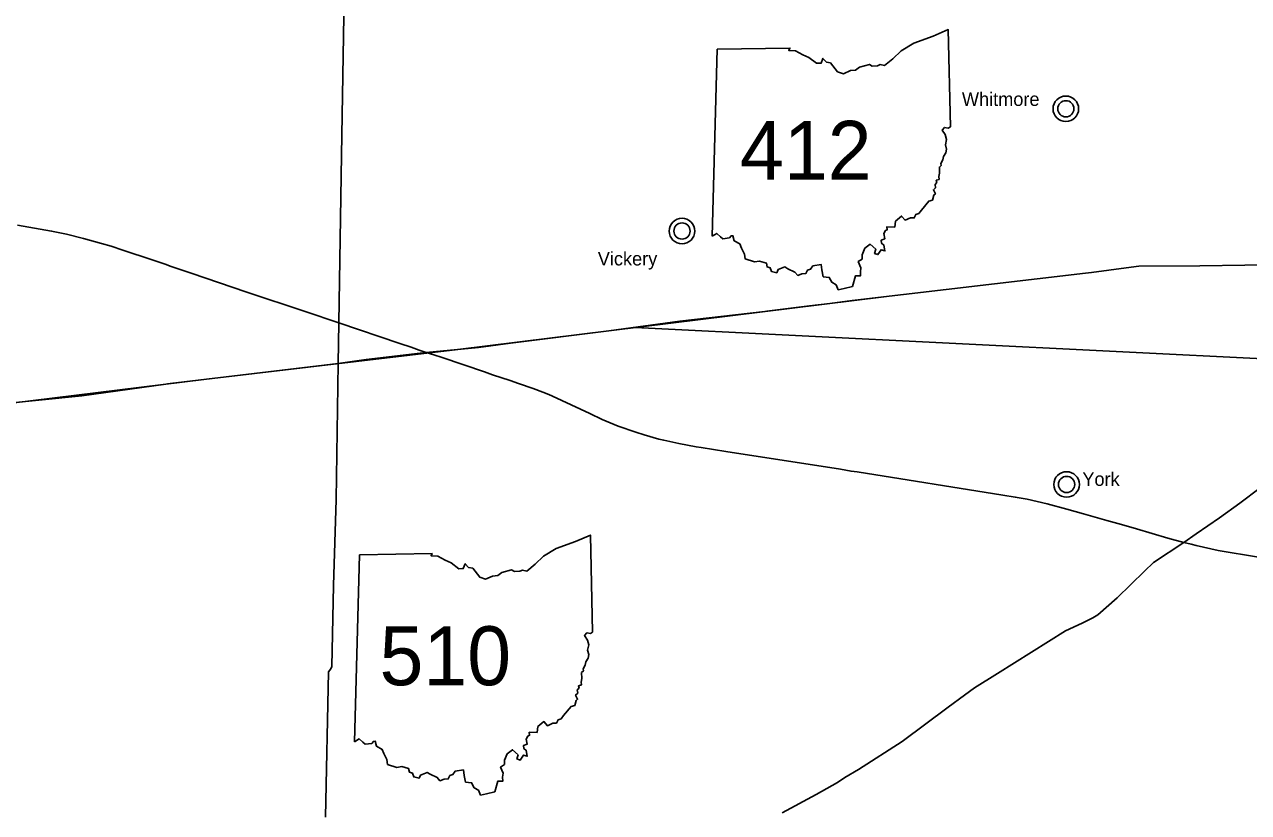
# Model space of a CAD drawing. Extents: x 0 to 798, y 0 to 440.
# Drawn here: x 446.4 to 540.4, y 195.7 to 256.2 of the extents above; entities that cross this region are included whole.
import ezdxf

# ---------------------------------------------------------------- set-up
doc = ezdxf.new("R2010")
doc.units = 0
for name, color, linetype in [('DV_X_Corp_Line', 7, 'Continuous'), ('GM_X_Interstate_Route', 7, 'Continuous'), ('GM_X_State_Route', 7, 'Continuous'), ('PV_P_Text', 7, 'Continuous'), ('SH_Data', 7, 'Continuous'), ('SH_Text', 7, 'Continuous')]:
    doc.layers.add(name, color=color, linetype=linetype)

msp = doc.modelspace()

# ---------------------------------------------------------------- linework, layer by layer
at = {"layer": 'DV_X_Corp_Line'}
for centre, radius in [((526.341, 249.752), 0.982), ((526.341, 249.752), 0.623), ((496.864, 240.36), 0.982), ((496.864, 240.36), 0.623), ((526.399, 220.893), 0.982), ((526.399, 220.893), 0.623)]:
    msp.add_circle(centre, radius, dxfattribs=at)
at = {"layer": 'GM_X_Interstate_Route'}
for points in [[(445.845, 240.82), (448.444, 240.358), (449.603, 240.115), (450.914, 239.792), (452.29, 239.407), (453.016, 239.192), (453.921, 238.897), (456.175, 238.137), (457.176, 237.804), (457.368, 237.73), (457.553, 237.674), (459.177, 237.127), (463.457, 235.671), (467.932, 234.185), (470.519, 233.299)], [(470.519, 233.299), (475.186, 231.729), (476.063, 231.433), (476.687, 231.22), (477.227, 231.041)], [(477.227, 231.041), (477.811, 230.84), (478.442, 230.637), (481.691, 229.535), (482.314, 229.323), (483.661, 228.872), (484.316, 228.656), (485.44, 228.259), (486.173, 227.973), (486.627, 227.791), (486.906, 227.668), (487.633, 227.346), (489.777, 226.332), (490.736, 225.881), (491.962, 225.383), (493.327, 224.902), (493.95, 224.699), (495.096, 224.383), (495.462, 224.29), (496.625, 224.031), (497.942, 223.795), (498.334, 223.739), (500.24, 223.434), (509.044, 222.058), (509.85, 221.913), (510.328, 221.85), (521.502, 220.07), (522.453, 219.927), (523.359, 219.75), (524.902, 219.406), (526.429, 219.001), (527.708, 218.647), (529.484, 218.129), (530.623, 217.805), (531.768, 217.472), (534.176, 216.778), (535.411, 216.436)], [(535.411, 216.436), (535.959, 216.296), (536.343, 216.195), (538.049, 215.818), (541.14, 215.309), (543.103, 215.027), (545.19, 214.727), (546.631, 214.512), (549.5, 214.099), (552.898, 213.603), (555.121, 213.284), (557.773, 212.9), (566.971, 211.135)]]:
    msp.add_lwpolyline(points, dxfattribs=at)
at = {"layer": 'GM_X_State_Route'}
msp.add_line((510.15, 235.049), (527.849, 237.123), dxfattribs=at)
for points in [[(469.488, 195.343), (469.722, 206.488), (469.906, 206.741), (469.984, 206.905), (470.105, 213.119), (470.31, 219.731), (470.468, 230.182), (470.519, 233.299), (470.702, 246.178), (471.047, 266.057)], [(527.849, 237.123), (528.301, 237.175), (530.968, 237.527), (531.941, 237.654), (536.639, 237.679), (540.086, 237.731), (543.32, 237.756), (545.306, 237.722), (545.783, 237.707), (546.098, 237.766), (546.711, 238.041), (547.144, 237.988), (548.24, 237.714), (552.16, 234.851), (553.376, 233.926), (554.473, 233.191), (556.089, 231.972), (556.243, 231.87), (556.425, 231.423)], [(476.972, 231.01), (477.227, 231.041), (481.223, 231.411), (483.689, 231.738), (491.253, 232.695), (496.687, 233.426), (503.225, 234.19), (503.37, 234.207), (506.663, 234.612), (508.227, 234.805), (509.934, 235.022)], [(509.934, 235.022), (509.954, 235.024), (510.15, 235.049)], [(535.411, 216.436), (536.355, 217.089), (538.148, 218.33), (539.714, 219.452), (541.254, 220.634), (544.23, 222.901), (546.831, 224.934), (548.888, 226.573), (551.092, 228.229), (552.014, 228.932), (552.448, 229.223), (553.861, 229.967), (556.425, 231.423)], [(470.468, 230.182), (472.603, 230.483), (476.972, 231.01)], [(457.362, 228.622), (457.567, 228.651), (470.468, 230.182)], [(443.735, 226.99), (444.137, 227.042), (450.764, 227.697), (457.232, 228.604), (457.362, 228.622)], [(504.554, 195.674), (507.169, 197.074), (508.795, 198.003), (509.377, 198.383), (510.427, 198.988), (513.768, 201.157), (517.301, 203.79), (518.57, 204.714), (519.33, 205.267), (521.083, 206.364), (526.312, 209.637), (527.594, 210.239), (528.422, 210.656), (528.796, 210.877), (530.281, 212.185), (532.387, 214.243), (533.076, 214.888), (535.411, 216.436)]]:
    msp.add_lwpolyline(points, dxfattribs=at)
at = {"layer": 'PV_P_Text'}
for p, q in [((499.171, 239.957), (499.573, 254.32)), ((499.171, 239.957), (499.573, 254.32)), ((471.701, 201.13), (472.103, 215.493)), ((471.701, 201.13), (472.103, 215.493))]:
    msp.add_line(p, q, dxfattribs=at)
for points in [[(499.573, 254.32), (505.145, 254.414), (505.058, 254.24), (505.584, 254.203), (506.143, 253.897), (506.615, 253.703), (507.193, 253.246), (507.539, 253.251), (507.685, 253.626), (507.95, 253.337), (508.264, 253.285), (508.807, 252.598), (509.256, 252.449), (509.793, 252.684), (510.194, 252.723), (510.488, 252.956), (511.252, 253.155), (511.466, 253.036), (511.87, 253.06), (512.074, 253.148), (512.427, 253.069), (513.049, 253.591), (513.689, 254.207), (514.673, 254.788), (516.143, 255.339), (517.305, 255.831), (517.473, 248.378)], [(499.573, 254.32), (505.145, 254.414), (505.058, 254.24), (505.584, 254.203), (506.143, 253.897), (506.615, 253.703), (507.193, 253.246), (507.539, 253.251), (507.685, 253.626), (507.95, 253.337), (508.264, 253.285), (508.807, 252.598), (509.256, 252.449), (509.793, 252.684), (510.194, 252.723), (510.488, 252.956), (511.252, 253.155), (511.466, 253.036), (511.87, 253.06), (512.074, 253.148), (512.427, 253.069), (513.049, 253.591), (513.689, 254.207), (514.673, 254.788), (516.143, 255.339), (517.305, 255.831), (517.473, 248.378)], [(517.473, 248.378), (517.302, 248.273), (517.035, 248.322), (516.855, 248.113), (517.077, 247.764), (517.182, 247.396), (517.089, 246.99), (517.181, 246.655), (517.119, 246.374), (516.951, 246.095), (516.893, 245.829), (516.75, 245.549), (516.762, 245.392), (516.626, 245.268), (516.651, 244.802), (516.582, 244.543), (516.605, 244.321), (516.385, 244.262), (516.435, 244.078), (516.295, 243.936), (516.325, 243.691), (516.166, 243.535), (516.32, 243.222), (516.196, 243.123), (516.093, 242.743), (515.81, 242.666), (515.244, 241.97), (515.044, 241.707), (514.819, 241.642), (514.695, 241.372), (514.419, 241.371), (514, 241.184), (513.729, 241.506), (513.255, 241.118), (513.201, 240.67), (512.601, 240.684), (512.625, 240.458), (512.491, 240.392), (512.369, 240.165), (512.44, 239.762), (512.159, 239.659), (512.193, 239.425), (512.373, 239.282), (512.453, 238.835), (512.154, 238.926), (511.91, 238.549), (511.659, 238.637), (511.741, 238.956), (511.317, 239.34), (510.915, 239.033), (510.705, 238.541), (510.703, 238.211), (510.404, 238.011), (510.596, 237.544), (510.561, 237.222), (510.566, 236.917), (510.192, 236.927), (509.966, 236.103)], [(517.473, 248.378), (517.302, 248.273), (517.035, 248.322), (516.855, 248.113), (517.077, 247.764), (517.182, 247.396), (517.089, 246.99), (517.181, 246.655), (517.119, 246.374), (516.951, 246.095), (516.893, 245.829), (516.75, 245.549), (516.762, 245.392), (516.626, 245.268), (516.651, 244.802), (516.582, 244.543), (516.605, 244.321), (516.385, 244.262), (516.435, 244.078), (516.295, 243.936), (516.325, 243.691), (516.166, 243.535), (516.32, 243.222), (516.196, 243.123), (516.093, 242.743), (515.81, 242.666), (515.244, 241.97), (515.044, 241.707), (514.819, 241.642), (514.695, 241.372), (514.419, 241.371), (514, 241.184), (513.729, 241.506), (513.255, 241.118), (513.201, 240.67), (512.601, 240.684), (512.625, 240.458), (512.491, 240.392), (512.369, 240.165), (512.44, 239.762), (512.159, 239.659), (512.193, 239.425), (512.373, 239.282), (512.453, 238.835), (512.154, 238.926), (511.91, 238.549), (511.659, 238.637), (511.741, 238.956), (511.317, 239.34), (510.915, 239.033), (510.705, 238.541), (510.703, 238.211), (510.404, 238.011), (510.596, 237.544), (510.561, 237.222), (510.566, 236.917), (510.192, 236.927), (509.966, 236.103)], [(509.966, 236.103), (509.315, 235.945), (508.864, 235.851), (508.705, 236.225), (508.382, 236.423), (508.172, 236.8), (507.708, 236.851), (507.598, 237.369), (507.547, 237.79), (506.913, 237.686), (506.739, 237.429), (506.514, 237.36), (506.384, 237.101), (506.077, 237.079), (505.748, 236.957), (505.533, 237.211), (504.994, 237.466), (504.752, 237.598), (504.246, 237.393), (504.138, 237.151), (503.735, 237.258), (503.64, 237.528), (503.396, 237.609), (503.342, 237.895), (502.821, 238.047), (502.422, 237.987), (501.719, 238.217), (501.676, 238.593), (501.436, 239.052), (501.311, 239.37), (500.866, 239.613), (500.776, 239.992), (500.634, 239.981), (500.504, 239.827), (500.01, 239.757), (499.813, 239.911), (499.536, 240.176), (499.171, 239.957)], [(509.966, 236.103), (509.315, 235.945), (508.864, 235.851), (508.705, 236.225), (508.382, 236.423), (508.172, 236.8), (507.708, 236.851), (507.598, 237.369), (507.547, 237.79), (506.913, 237.686), (506.739, 237.429), (506.514, 237.36), (506.384, 237.101), (506.077, 237.079), (505.748, 236.957), (505.533, 237.211), (504.994, 237.466), (504.752, 237.598), (504.246, 237.393), (504.138, 237.151), (503.735, 237.258), (503.64, 237.528), (503.396, 237.609), (503.342, 237.895), (502.821, 238.047), (502.422, 237.987), (501.719, 238.217), (501.676, 238.593), (501.436, 239.052), (501.311, 239.37), (500.866, 239.613), (500.776, 239.992), (500.634, 239.981), (500.504, 239.827), (500.01, 239.757), (499.813, 239.911), (499.536, 240.176), (499.171, 239.957)], [(472.103, 215.493), (477.675, 215.587), (477.588, 215.413), (478.114, 215.376), (478.673, 215.07), (479.145, 214.876), (479.723, 214.419), (480.069, 214.424), (480.215, 214.799), (480.48, 214.51), (480.794, 214.458), (481.337, 213.771), (481.786, 213.622), (482.323, 213.857), (482.724, 213.896), (483.017, 214.129), (483.782, 214.328), (483.996, 214.209), (484.4, 214.233), (484.604, 214.321), (484.957, 214.242), (485.579, 214.765), (486.219, 215.38), (487.203, 215.961), (488.673, 216.512), (489.835, 217.004), (490.003, 209.551)], [(472.103, 215.493), (477.675, 215.587), (477.588, 215.413), (478.114, 215.376), (478.673, 215.07), (479.145, 214.876), (479.723, 214.419), (480.069, 214.424), (480.215, 214.799), (480.48, 214.51), (480.794, 214.458), (481.337, 213.771), (481.786, 213.622), (482.323, 213.857), (482.724, 213.896), (483.017, 214.129), (483.782, 214.328), (483.996, 214.209), (484.4, 214.233), (484.604, 214.321), (484.957, 214.242), (485.579, 214.765), (486.219, 215.38), (487.203, 215.961), (488.673, 216.512), (489.835, 217.004), (490.003, 209.551)], [(490.003, 209.551), (489.832, 209.446), (489.565, 209.495), (489.385, 209.286), (489.607, 208.937), (489.712, 208.569), (489.619, 208.163), (489.711, 207.828), (489.649, 207.547), (489.481, 207.268), (489.423, 207.002), (489.28, 206.722), (489.292, 206.565), (489.156, 206.441), (489.181, 205.975), (489.112, 205.716), (489.135, 205.494), (488.915, 205.435), (488.965, 205.251), (488.825, 205.109), (488.855, 204.864), (488.696, 204.708), (488.85, 204.396), (488.726, 204.296), (488.623, 203.916), (488.34, 203.839), (487.774, 203.143), (487.574, 202.88), (487.349, 202.815), (487.225, 202.545), (486.949, 202.544), (486.53, 202.357), (486.259, 202.679), (485.785, 202.291), (485.731, 201.843), (485.131, 201.857), (485.155, 201.631), (485.021, 201.565), (484.899, 201.338), (484.97, 200.935), (484.689, 200.833), (484.723, 200.598), (484.903, 200.455), (484.983, 200.008), (484.684, 200.099), (484.44, 199.722), (484.189, 199.81), (484.271, 200.13), (483.847, 200.513), (483.445, 200.206), (483.235, 199.715), (483.233, 199.384), (482.934, 199.184), (483.126, 198.717), (483.091, 198.395), (483.096, 198.09), (482.722, 198.101), (482.496, 197.276)], [(490.003, 209.551), (489.832, 209.446), (489.565, 209.495), (489.385, 209.286), (489.607, 208.937), (489.712, 208.569), (489.619, 208.163), (489.711, 207.828), (489.649, 207.547), (489.481, 207.268), (489.423, 207.002), (489.28, 206.722), (489.292, 206.565), (489.156, 206.441), (489.181, 205.975), (489.112, 205.716), (489.135, 205.494), (488.915, 205.435), (488.965, 205.251), (488.825, 205.109), (488.855, 204.864), (488.696, 204.708), (488.85, 204.396), (488.726, 204.296), (488.623, 203.916), (488.34, 203.839), (487.774, 203.143), (487.574, 202.88), (487.349, 202.815), (487.225, 202.545), (486.949, 202.544), (486.53, 202.357), (486.259, 202.679), (485.785, 202.291), (485.731, 201.843), (485.131, 201.857), (485.155, 201.631), (485.021, 201.565), (484.899, 201.338), (484.97, 200.935), (484.689, 200.833), (484.723, 200.598), (484.903, 200.455), (484.983, 200.008), (484.684, 200.099), (484.44, 199.722), (484.189, 199.81), (484.271, 200.13), (483.847, 200.513), (483.445, 200.206), (483.235, 199.715), (483.233, 199.384), (482.934, 199.184), (483.126, 198.717), (483.091, 198.395), (483.096, 198.09), (482.722, 198.101), (482.496, 197.276)], [(482.496, 197.276), (481.845, 197.118), (481.394, 197.024), (481.235, 197.399), (480.912, 197.596), (480.702, 197.973), (480.238, 198.025), (480.128, 198.542), (480.077, 198.963), (479.443, 198.859), (479.269, 198.602), (479.044, 198.533), (478.913, 198.274), (478.607, 198.252), (478.278, 198.13), (478.063, 198.384), (477.524, 198.639), (477.282, 198.771), (476.776, 198.566), (476.668, 198.324), (476.265, 198.431), (476.17, 198.701), (475.926, 198.782), (475.872, 199.068), (475.351, 199.22), (474.952, 199.16), (474.249, 199.39), (474.206, 199.766), (473.966, 200.225), (473.841, 200.543), (473.396, 200.787), (473.306, 201.165), (473.164, 201.154), (473.034, 201), (472.54, 200.93), (472.343, 201.085), (472.066, 201.349), (471.701, 201.13)], [(482.496, 197.276), (481.845, 197.118), (481.394, 197.024), (481.235, 197.399), (480.912, 197.596), (480.702, 197.973), (480.238, 198.025), (480.128, 198.542), (480.077, 198.963), (479.443, 198.859), (479.269, 198.602), (479.044, 198.533), (478.913, 198.274), (478.607, 198.252), (478.278, 198.13), (478.063, 198.384), (477.524, 198.639), (477.282, 198.771), (476.776, 198.566), (476.668, 198.324), (476.265, 198.431), (476.17, 198.701), (475.926, 198.782), (475.872, 199.068), (475.351, 199.22), (474.952, 199.16), (474.249, 199.39), (474.206, 199.766), (473.966, 200.225), (473.841, 200.543), (473.396, 200.787), (473.306, 201.165), (473.164, 201.154), (473.034, 201), (472.54, 200.93), (472.343, 201.085), (472.066, 201.349), (471.701, 201.13)]]:
    msp.add_lwpolyline(points, dxfattribs=at)
at = {"layer": 'SH_Data'}
msp.add_line((569.322, 229.171), (493.271, 232.949), dxfattribs=at)
at = {"layer": 'SH_Text'}
msp.add_lwpolyline([(398.463, 218.595), (406.122, 220.119), (411.598, 221.05), (417.281, 222.017), (420.662, 222.844), (429.974, 225.15), (431.252, 225.43), (436.834, 226.079), (460.336, 228.979), (479.647, 231.265), (512.371, 235.309)], dxfattribs=at)

# ---------------------------------------------------------------- texts
at = {"layer": 'DV_X_Corp_Line'}
for s, p in [('Whitmore', (518.36, 249.97)), ('Vickery', (490.398, 237.716)), ('York', (527.61, 220.785))]:
    msp.add_text(s, height=1.0417, rotation=0.00001, dxfattribs=at).set_placement(p)
at = {"layer": 'PV_P_Text'}
for s, p in [('412', (501.319, 244.295)), ('510', (473.635, 205.468))]:
    msp.add_text(s, height=4.5281, dxfattribs=at).set_placement(p)

doc.saveas('drawing.dxf')
